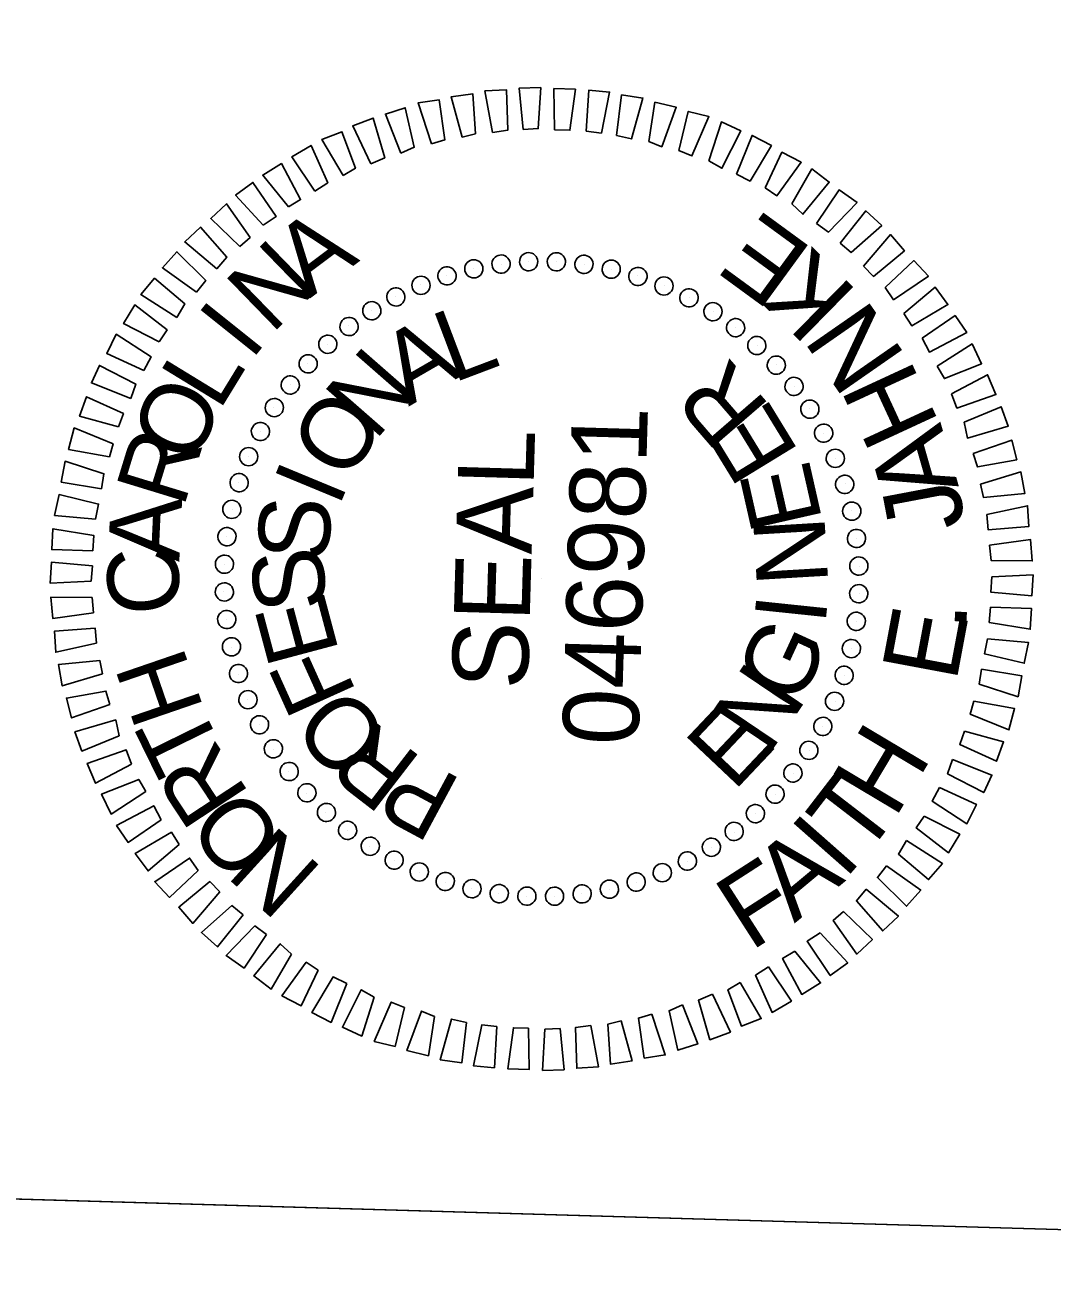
# Model space of a CAD drawing. Extents: x 2097000 to 2098148, y 684979 to 687012.
# Drawn here: x 2097111.3 to 2097192.5, y 686617.1 to 686715.9 of the extents above; entities that cross this region are included whole.
import ezdxf

# ---------------------------------------------------------------- set-up
doc = ezdxf.new("R2010")
doc.units = 0
for name, color, linetype in [('Sheet Layout Plan Border', 7, 'Continuous'), ('Sheet PE Seal Cell', 7, 'Continuous'), ('Sheet Profile CELL', 7, 'Continuous')]:
    doc.layers.add(name, color=color, linetype=linetype)

msp = doc.modelspace()

# ---------------------------------------------------------------- linework, layer by layer
at = {"layer": 'Sheet Layout Plan Border'}
msp.add_lwpolyline([(2098090.846, 685704.417), (2097236.932, 685318.955), (2097029.373, 685324.989), (2097067.147, 686624.39), (2097254.374, 686618.947), (2097261.847, 686618.73), (2097260.988, 686589.187), (2097439.335, 686584.003), (2097443.487, 686726.823), (2098119.997, 686707.157)], close=True, dxfattribs=at)
at = {"layer": 'Sheet PE Seal Cell'}
for p, q in [((2097146.767, 686696.627), (2097146.767, 686696.627)), ((2097148.978, 686696.963), (2097148.978, 686696.963)), ((2097151.135, 686697.2), (2097151.135, 686697.2)), ((2097153.336, 686697.187), (2097153.336, 686697.187)), ((2097155.531, 686696.973), (2097155.531, 686696.973)), ((2097157.669, 686696.56), (2097157.669, 686696.56)), ((2097144.65, 686696.088), (2097144.65, 686696.088)), ((2097159.756, 686696.05), (2097159.756, 686696.05)), ((2097142.628, 686695.347), (2097142.628, 686695.347)), ((2097161.834, 686695.289), (2097161.834, 686695.289)), ((2097140.65, 686694.404), (2097140.65, 686694.404)), ((2097163.807, 686694.331), (2097163.807, 686694.331)), ((2097138.717, 686693.31), (2097138.717, 686693.31)), ((2097165.727, 686693.275), (2097165.727, 686693.275)), ((2097136.931, 686692.111), (2097136.931, 686692.111)), ((2097167.49, 686691.973), (2097167.49, 686691.973)), ((2097135.239, 686690.66), (2097135.239, 686690.66)), ((2097169.2, 686690.573), (2097169.2, 686690.573)), ((2097133.694, 686689.154), (2097133.694, 686689.154)), ((2097170.706, 686689.028), (2097170.706, 686689.028)), ((2097132.294, 686687.444), (2097132.294, 686687.444)), ((2097172.158, 686687.335), (2097172.158, 686687.335)), ((2097130.992, 686685.681), (2097130.992, 686685.681)), ((2097173.356, 686685.55), (2097173.356, 686685.55)), ((2097129.936, 686683.761), (2097129.936, 686683.761)), ((2097174.45, 686683.617), (2097174.45, 686683.617)), ((2097128.978, 686681.788), (2097128.978, 686681.788)), ((2097175.393, 686681.639), (2097175.393, 686681.639)), ((2097128.217, 686679.709), (2097128.217, 686679.709)), ((2097176.135, 686679.617), (2097176.135, 686679.617)), ((2097127.707, 686677.623), (2097127.707, 686677.623)), ((2097176.674, 686677.5), (2097176.674, 686677.5)), ((2097127.294, 686675.484), (2097127.294, 686675.484)), ((2097177.01, 686675.289), (2097177.01, 686675.289)), ((2097127.08, 686673.289), (2097127.08, 686673.289)), ((2097177.247, 686673.132), (2097177.247, 686673.132)), ((2097152.157, 686672.11), (2097152.157, 686672.11)), ((2097127.066, 686671.089), (2097127.066, 686671.089)), ((2097177.233, 686670.931), (2097177.233, 686670.931)), ((2097127.304, 686668.931), (2097127.304, 686668.931)), ((2097177.019, 686668.736), (2097177.019, 686668.736)), ((2097127.64, 686666.72), (2097127.64, 686666.72)), ((2097176.607, 686666.597), (2097176.607, 686666.597)), ((2097128.178, 686664.604), (2097128.178, 686664.604)), ((2097176.096, 686664.511), (2097176.096, 686664.511)), ((2097128.92, 686662.581), (2097128.92, 686662.581)), ((2097175.335, 686662.433), (2097175.335, 686662.433)), ((2097129.863, 686660.603), (2097129.863, 686660.603)), ((2097174.377, 686660.46), (2097174.377, 686660.46)), ((2097130.957, 686658.671), (2097130.957, 686658.671)), ((2097173.321, 686658.539), (2097173.321, 686658.539)), ((2097132.156, 686656.885), (2097132.156, 686656.885)), ((2097172.019, 686656.777), (2097172.019, 686656.777)), ((2097133.607, 686655.192), (2097133.607, 686655.192)), ((2097170.619, 686655.067), (2097170.619, 686655.067)), ((2097135.113, 686653.648), (2097135.113, 686653.648)), ((2097169.075, 686653.561), (2097169.075, 686653.561)), ((2097136.823, 686652.247), (2097136.823, 686652.247)), ((2097167.382, 686652.109), (2097167.382, 686652.109)), ((2097138.586, 686650.946), (2097138.586, 686650.946)), ((2097165.596, 686650.911), (2097165.596, 686650.911)), ((2097140.506, 686649.889), (2097140.506, 686649.889)), ((2097163.664, 686649.816), (2097163.664, 686649.816)), ((2097142.479, 686648.932), (2097142.479, 686648.932)), ((2097144.558, 686648.171), (2097144.558, 686648.171)), ((2097159.663, 686648.132), (2097159.663, 686648.132)), ((2097161.685, 686648.873), (2097161.685, 686648.873)), ((2097146.644, 686647.66), (2097146.644, 686647.66)), ((2097148.783, 686647.248), (2097148.783, 686647.248)), ((2097155.336, 686647.257), (2097155.336, 686647.257)), ((2097157.547, 686647.593), (2097157.547, 686647.593)), ((2097150.977, 686647.034), (2097150.977, 686647.034)), ((2097153.178, 686647.02), (2097153.178, 686647.02))]:
    msp.add_line(p, q, dxfattribs=at)
for points in [[(2097145.868, 686707.008), (2097145.01, 686710.184), (2097146.718, 686710.434), (2097146.926, 686707.277)], [(2097148.28, 686707.388), (2097147.675, 686710.657), (2097149.379, 686710.757), (2097149.485, 686707.553)], [(2097150.688, 686707.618), (2097150.382, 686710.878), (2097152.085, 686710.929), (2097151.89, 686707.683)], [(2097153.188, 686707.595), (2097153.133, 686710.848), (2097154.832, 686710.799), (2097154.388, 686707.56)], [(2097155.686, 686707.473), (2097155.88, 686710.718), (2097157.527, 686710.57), (2097156.882, 686707.338)], [(2097158.077, 686707.153), (2097158.47, 686710.343), (2097160.164, 686710.094), (2097159.27, 686706.868)], [(2097143.452, 686706.478), (2097142.395, 686709.71), (2097144.053, 686709.962), (2097144.511, 686706.797)], [(2097160.615, 686706.679), (2097161.105, 686709.766), (2097162.794, 686709.367), (2097161.653, 686706.249)], [(2097138.654, 686704.916), (2097137.241, 686707.909), (2097138.859, 686708.512), (2097139.768, 686705.384)], [(2097141.029, 686705.748), (2097139.819, 686708.834), (2097141.384, 686709.339), (2097142.094, 686706.217)], [(2097162.995, 686705.96), (2097163.735, 686709.039), (2097165.374, 686708.642), (2097164.033, 686705.529)], [(2097136.476, 686703.979), (2097134.808, 686706.829), (2097136.376, 686707.434), (2097137.443, 686704.551)], [(2097165.372, 686705.14), (2097166.362, 686708.213), (2097167.892, 686707.518), (2097166.406, 686704.56)], [(2097167.542, 686704.077), (2097168.782, 686707.142), (2097170.309, 686706.347), (2097168.627, 686703.545)], [(2097134.239, 686702.744), (2097132.417, 686705.448), (2097133.944, 686706.354), (2097135.259, 686703.414)], [(2097169.812, 686703.01), (2097171.144, 686705.823), (2097172.672, 686705.028), (2097170.744, 686702.383)], [(2097132.152, 686701.504), (2097130.124, 686704.014), (2097131.601, 686704.921), (2097133.119, 686702.076)], [(2097171.926, 686701.748), (2097173.507, 686704.503), (2097174.877, 686703.463), (2097172.803, 686700.922)], [(2097130.16, 686700.061), (2097127.977, 686702.426), (2097129.357, 686703.436), (2097131.18, 686700.732)], [(2097173.882, 686700.191), (2097175.66, 686702.84), (2097177.081, 686701.848), (2097174.813, 686699.513)], [(2097128.309, 686698.364), (2097126.023, 686700.582), (2097127.257, 686701.746), (2097129.131, 686699.091)], [(2097175.737, 686698.636), (2097177.762, 686701.178), (2097179.03, 686700.041), (2097176.617, 686697.91)], [(2097126.508, 686696.616), (2097123.969, 686698.741), (2097125.203, 686699.905), (2097127.285, 686697.544)], [(2097177.586, 686696.832), (2097179.709, 686699.321), (2097180.822, 686698.038), (2097178.362, 686696.009)], [(2097124.903, 686694.762), (2097122.208, 686696.691), (2097123.346, 686697.958), (2097125.631, 686695.691)], [(2097179.287, 686695.132), (2097181.55, 686697.267), (2097182.715, 686696.032), (2097179.959, 686694.162)], [(2097123.344, 686692.756), (2097120.497, 686694.59), (2097121.584, 686695.859), (2097123.976, 686693.838)], [(2097180.778, 686693.087), (2097183.24, 686695.167), (2097184.25, 686693.787), (2097181.4, 686692.119)], [(2097121.938, 686690.846), (2097119.129, 686692.278), (2097120.022, 686693.753), (2097122.566, 686691.778)], [(2097182.222, 686691.145), (2097184.825, 686692.92), (2097185.737, 686691.593), (2097182.79, 686690.028)], [(2097120.722, 686688.581), (2097117.81, 686689.916), (2097118.554, 686691.445), (2097121.304, 686689.664)], [(2097183.408, 686688.909), (2097186.161, 686690.68), (2097186.915, 686689.107), (2097183.98, 686687.942)], [(2097119.707, 686686.359), (2097116.592, 686687.6), (2097117.232, 686688.982), (2097120.09, 686687.499)], [(2097184.545, 686686.725), (2097187.39, 686688.243), (2097188.045, 686686.673), (2097184.963, 686685.613)], [(2097118.742, 686684.136), (2097115.665, 686684.976), (2097116.21, 686686.511), (2097119.122, 686685.176)], [(2097185.531, 686684.496), (2097188.467, 686685.711), (2097189.023, 686684.194), (2097185.794, 686683.237)], [(2097118.023, 686681.756), (2097114.788, 686682.35), (2097115.238, 686684.038), (2097118.303, 686682.798)], [(2097186.259, 686682.023), (2097189.291, 686683.086), (2097189.696, 686681.523), (2097186.578, 686680.964)], [(2097117.399, 686679.223), (2097114.213, 686679.766), (2097114.511, 686681.408), (2097117.583, 686680.418)], [(2097186.839, 686679.606), (2097190.018, 686680.564), (2097190.319, 686678.854), (2097187.058, 686678.549)], [(2097116.929, 686676.836), (2097113.686, 686677.13), (2097114.034, 686678.771), (2097117.164, 686678.03)], [(2097187.319, 686677.191), (2097190.541, 686677.897), (2097190.643, 686676.244), (2097187.434, 686675.987)], [(2097116.707, 686674.341), (2097113.458, 686674.436), (2097113.556, 686676.084), (2097116.791, 686675.539)], [(2097187.549, 686674.783), (2097190.764, 686675.24), (2097190.914, 686673.535), (2097187.664, 686673.579)], [(2097116.587, 686671.944), (2097113.331, 686671.788), (2097113.429, 686673.436), (2097116.672, 686673.142)], [(2097187.727, 686672.277), (2097190.982, 686672.432), (2097190.884, 686670.784), (2097187.642, 686671.079)], [(2097116.764, 686669.438), (2097113.549, 686668.981), (2097113.399, 686670.686), (2097116.649, 686670.641)], [(2097187.607, 686669.879), (2097190.855, 686669.785), (2097190.758, 686668.137), (2097187.522, 686668.681)], [(2097116.994, 686667.03), (2097113.772, 686666.323), (2097113.67, 686667.977), (2097116.879, 686668.234)], [(2097187.384, 686667.385), (2097190.627, 686667.09), (2097190.279, 686665.45), (2097187.149, 686666.191)], [(2097117.474, 686664.615), (2097114.295, 686663.657), (2097113.995, 686665.366), (2097117.255, 686665.672)], [(2097186.915, 686664.997), (2097190.1, 686664.454), (2097189.802, 686662.812), (2097186.73, 686663.802)], [(2097118.054, 686662.197), (2097115.022, 686661.135), (2097114.617, 686662.697), (2097117.735, 686663.257)], [(2097186.291, 686662.464), (2097189.525, 686661.87), (2097189.076, 686660.182), (2097186.01, 686661.422)], [(2097118.783, 686659.725), (2097115.846, 686658.51), (2097115.29, 686660.026), (2097118.519, 686660.983)], [(2097185.571, 686660.084), (2097188.648, 686659.244), (2097188.103, 686657.71), (2097185.191, 686659.045)], [(2097119.768, 686657.495), (2097116.923, 686655.977), (2097116.268, 686657.547), (2097119.35, 686658.608)], [(2097184.606, 686657.861), (2097187.722, 686656.62), (2097187.081, 686655.238), (2097184.223, 686656.722)], [(2097120.905, 686655.311), (2097118.153, 686653.54), (2097117.398, 686655.113), (2097120.333, 686656.278)], [(2097183.591, 686655.64), (2097186.504, 686654.305), (2097185.759, 686652.776), (2097183.01, 686654.556)], [(2097122.091, 686653.076), (2097119.488, 686651.301), (2097118.576, 686652.628), (2097121.523, 686654.193)], [(2097182.375, 686653.374), (2097185.185, 686651.942), (2097184.291, 686650.467), (2097181.748, 686652.442)], [(2097123.535, 686651.133), (2097121.074, 686649.054), (2097120.063, 686650.434), (2097122.913, 686652.102)], [(2097180.969, 686651.464), (2097183.817, 686649.631), (2097182.729, 686648.362), (2097180.337, 686650.382)], [(2097125.026, 686649.089), (2097122.763, 686646.954), (2097121.599, 686648.188), (2097124.354, 686650.059)], [(2097179.41, 686649.459), (2097182.105, 686647.53), (2097180.968, 686646.262), (2097178.683, 686648.529)], [(2097126.728, 686647.389), (2097124.604, 686644.899), (2097123.491, 686646.182), (2097125.951, 686648.212)], [(2097177.805, 686647.605), (2097180.345, 686645.48), (2097179.11, 686644.315), (2097177.028, 686646.677)], [(2097128.576, 686645.584), (2097126.551, 686643.042), (2097125.284, 686644.179), (2097127.697, 686646.31)], [(2097176.004, 686645.856), (2097178.29, 686643.639), (2097177.056, 686642.474), (2097175.182, 686645.13)], [(2097130.432, 686644.03), (2097128.654, 686641.38), (2097127.232, 686642.372), (2097129.501, 686644.707)], [(2097132.387, 686642.472), (2097130.806, 686639.717), (2097129.436, 686640.757), (2097131.511, 686643.298)], [(2097174.154, 686644.159), (2097176.336, 686641.795), (2097174.956, 686640.784), (2097173.134, 686643.489)], [(2097172.161, 686642.716), (2097174.189, 686640.207), (2097172.712, 686639.299), (2097171.194, 686642.144)], [(2097134.501, 686641.21), (2097133.169, 686638.398), (2097131.641, 686639.192), (2097133.569, 686641.838)], [(2097170.074, 686641.477), (2097171.896, 686638.773), (2097170.369, 686637.867), (2097169.054, 686640.806)], [(2097136.771, 686640.144), (2097135.532, 686637.079), (2097134.004, 686637.873), (2097135.686, 686640.676)], [(2097167.837, 686640.241), (2097169.505, 686637.391), (2097167.937, 686636.787), (2097166.87, 686639.669)], [(2097138.941, 686639.08), (2097137.952, 686636.008), (2097136.421, 686636.703), (2097137.908, 686639.661)], [(2097165.659, 686639.304), (2097167.073, 686636.312), (2097165.454, 686635.708), (2097164.545, 686638.836)], [(2097141.318, 686638.261), (2097140.579, 686635.181), (2097138.94, 686635.579), (2097140.281, 686638.691)], [(2097163.284, 686638.473), (2097164.495, 686635.386), (2097162.929, 686634.881), (2097162.22, 686638.003)], [(2097143.699, 686637.541), (2097143.209, 686634.454), (2097141.52, 686634.854), (2097142.661, 686637.972)], [(2097146.236, 686637.067), (2097145.843, 686633.878), (2097144.15, 686634.127), (2097145.044, 686637.352)], [(2097160.862, 686637.743), (2097161.918, 686634.511), (2097160.26, 686634.259), (2097159.802, 686637.423)], [(2097148.628, 686636.748), (2097148.433, 686633.502), (2097146.787, 686633.65), (2097147.431, 686636.883)], [(2097151.125, 686636.625), (2097151.181, 686633.372), (2097149.481, 686633.422), (2097149.926, 686636.66)], [(2097153.625, 686636.603), (2097153.931, 686633.342), (2097152.229, 686633.292), (2097152.423, 686636.537)], [(2097156.033, 686636.833), (2097156.638, 686633.564), (2097154.935, 686633.463), (2097154.828, 686636.668)], [(2097158.445, 686637.213), (2097159.303, 686634.036), (2097157.595, 686633.786), (2097157.387, 686636.943)]]:
    msp.add_lwpolyline(points, close=True, dxfattribs=at)
for centre, major_axis in [((2097148.955, 686696.985), (-0.092, 0.714)), ((2097151.135, 686697.169), (-0.029, 0.719)), ((2097153.323, 686697.163), (0.033, 0.719)), ((2097155.502, 686696.966), (0.096, 0.714)), ((2097144.684, 686696.051), (-0.215, 0.687)), ((2097146.799, 686696.611), (-0.154, 0.703)), ((2097157.656, 686696.58), (0.158, 0.702)), ((2097159.767, 686696.008), (0.218, 0.686)), ((2097142.626, 686695.309), (-0.274, 0.666)), ((2097161.821, 686695.253), (0.277, 0.664)), ((2097140.64, 686694.39), (-0.331, 0.64)), ((2097163.801, 686694.323), (0.334, 0.638)), ((2097138.742, 686693.301), (-0.385, 0.608)), ((2097165.693, 686693.224), (0.389, 0.606)), ((2097136.946, 686692.051), (-0.437, 0.572)), ((2097167.482, 686691.963), (0.44, 0.57)), ((2097135.266, 686690.65), (-0.485, 0.532)), ((2097169.154, 686690.552), (0.488, 0.529)), ((2097133.715, 686689.107), (-0.529, 0.488)), ((2097170.696, 686689.001), (0.532, 0.485)), ((2097132.303, 686687.435), (-0.57, 0.44)), ((2097172.098, 686687.321), (0.572, 0.437)), ((2097131.043, 686685.647), (-0.606, 0.389)), ((2097173.348, 686685.525), (0.608, 0.385)), ((2097129.944, 686683.755), (-0.638, 0.334)), ((2097174.436, 686683.627), (0.64, 0.331)), ((2097129.014, 686681.775), (-0.664, 0.277)), ((2097175.355, 686681.641), (0.666, 0.274)), ((2097128.259, 686679.721), (-0.686, 0.218)), ((2097176.098, 686679.583), (0.687, 0.215)), ((2097127.687, 686677.609), (-0.702, 0.158)), ((2097176.658, 686677.468), (0.703, 0.154)), ((2097127.301, 686675.455), (-0.714, 0.096)), ((2097177.031, 686675.312), (0.714, 0.092)), ((2097127.104, 686673.276), (-0.719, 0.033)), ((2097177.216, 686673.132), (0.719, 0.029)), ((2097127.097, 686671.088), (-0.719, -0.029)), ((2097177.21, 686670.944), (0.719, -0.033)), ((2097127.282, 686668.908), (-0.714, -0.092)), ((2097177.013, 686668.765), (0.714, -0.096)), ((2097127.656, 686666.753), (-0.703, -0.154)), ((2097176.626, 686666.611), (0.702, -0.158)), ((2097128.216, 686664.637), (-0.687, -0.215)), ((2097176.054, 686664.5), (0.686, -0.218)), ((2097128.958, 686662.579), (-0.666, -0.274)), ((2097175.3, 686662.446), (0.664, -0.277)), ((2097129.877, 686660.594), (-0.64, -0.331)), ((2097174.369, 686660.465), (0.638, -0.334)), ((2097130.966, 686658.696), (-0.608, -0.385)), ((2097173.27, 686658.574), (0.606, -0.389)), ((2097132.215, 686656.9), (-0.572, -0.437)), ((2097172.01, 686656.785), (0.57, -0.44)), ((2097133.617, 686655.22), (-0.532, -0.485)), ((2097170.599, 686655.113), (0.529, -0.488)), ((2097135.16, 686653.668), (-0.488, -0.529)), ((2097169.047, 686653.571), (0.485, -0.532)), ((2097136.832, 686652.257), (-0.44, -0.57)), ((2097167.367, 686652.169), (0.437, -0.572)), ((2097138.62, 686650.997), (-0.389, -0.606)), ((2097165.571, 686650.919), (0.385, -0.608)), ((2097140.512, 686649.897), (-0.334, -0.638)), ((2097163.673, 686649.831), (0.331, -0.64)), ((2097142.492, 686648.967), (-0.277, -0.664)), ((2097161.688, 686648.912), (0.274, -0.666)), ((2097144.546, 686648.213), (-0.218, -0.686)), ((2097146.658, 686647.64), (-0.158, -0.702)), ((2097157.514, 686647.609), (0.154, -0.703)), ((2097159.629, 686648.169), (0.215, -0.687)), ((2097148.811, 686647.254), (-0.096, -0.714)), ((2097150.99, 686647.057), (-0.033, -0.719)), ((2097153.178, 686647.051), (0.029, -0.719)), ((2097155.359, 686647.235), (0.092, -0.714))]:
    msp.add_ellipse(centre, major_axis=major_axis, ratio=0.999708, dxfattribs=at)
at = {"layer": 'Sheet Profile CELL'}
msp.add_lwpolyline([(2097092.187, 686623.662), (2097095.094, 686723.67), (2097207.547, 686720.401), (2097204.639, 686620.393)], close=True, dxfattribs=at)

# ---------------------------------------------------------------- texts
at = {"layer": 'Sheet PE Seal Cell'}
for s, height, rotation, p in [('A', 5.639, 36.95198, (2097133.842, 686694.252)), ('E', 5.998, 143.82785, (2097173.713, 686698.097)), ('N', 5.639, 44.15374, (2097130.808, 686691.389)), ('K', 5.998, 135.54393, (2097177.232, 686694.72)), ('I', 5.638, 51.35497, (2097129.196, 686689.285)), ('N', 5.998, 124.8181, (2097181.002, 686689.658)), ('L', 5.639, 20.73568, (2097145.153, 686687.57)), ('A', 5.639, 30.0951, (2097141.648, 686685.721)), ('N', 5.639, 48.81144, (2097138.966, 686682.948)), ('L', 5.638, 58.5557, (2097126.679, 686685.306)), ('R', 5.639, 130.81624, (2097170.309, 686685.688)), ('H', 5.998, 114.83412, (2097183.607, 686684.391)), ('O', 5.638, 65.75599, (2097124.702, 686680.962)), ('O', 5.638, 58.16831, (2097136.87, 686679.658)), ('E', 5.638, 121.45892, (2097172.555, 686682.072)), ('046981', 5.9982, 88.33483, (2097159.785, 686658.912)), ('R', 5.638, 72.95593, (2097123.855, 686677.635)), ('A', 5.998, 105.99381, (2097185.121, 686679.412)), ('SEAL', 5.9982, 88.33483, (2097151.053, 686663.34)), ('I', 5.638, 67.52443, (2097136.112, 686677.679)), ('E', 5.638, 102.74659, (2097174.35, 686676.717)), ('J', 5.998, 100.73599, (2097185.652, 686676.361)), ('A', 5.638, 87.35515, (2097123.533, 686673.443)), ('S', 5.638, 86.23523, (2097135.287, 686673.401)), ('N', 5.638, 93.39122, (2097174.806, 686671.752)), ('C', 5.638, 94.5547, (2097123.718, 686669.485)), ('S', 5.638, 95.59044, (2097135.232, 686669.801)), ('E', 5.638, 104.9459, (2097136.182, 686666.322)), ('I', 5.638, 84.03603, (2097174.559, 686668.408)), ('E', 5.998, 79.39252, (2097184.901, 686663.878)), ('.', 5.998, 86.50186, (2097185.668, 686667.994)), ('G', 5.638, 65.32507, (2097172.469, 686661.916)), ('H', 5.638, 108.95431, (2097125.497, 686661.831)), ('F', 5.638, 114.30186, (2097137.588, 686663.08)), ('N', 5.639, 55.96879, (2097170.11, 686658.183)), ('O', 5.639, 133.01607, (2097140.441, 686659.695)), ('E', 5.638, 46.61172, (2097167.323, 686655.262)), ('R', 5.639, 142.37448, (2097142.839, 686657.875)), ('T', 5.638, 116.1546, (2097127.052, 686658.534)), ('H', 5.998, 59.20818, (2097180.05, 686653.086)), ('R', 5.639, 123.35534, (2097129.152, 686655.071)), ('T', 5.998, 52.40794, (2097177.601, 686649.917)), ('P', 5.639, 151.73372, (2097145.991, 686656.183)), ('O', 5.639, 130.55657, (2097132.15, 686651.533)), ('I', 5.998, 48.60599, (2097176.074, 686648.278)), ('N', 5.639, 137.75833, (2097134.982, 686649.15)), ('A', 5.998, 39.76568, (2097172.127, 686644.886)), ('F', 5.998, 32.74907, (2097168.652, 686642.65))]:
    msp.add_text(s, height=height, rotation=rotation, dxfattribs=at).set_placement(p)

doc.saveas('drawing.dxf')
